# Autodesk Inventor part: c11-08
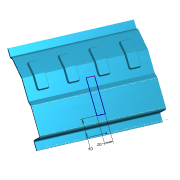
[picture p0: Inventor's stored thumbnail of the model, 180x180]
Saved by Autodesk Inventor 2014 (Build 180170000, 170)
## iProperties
Created: 2011-01
Part Number: c11-08
Material: Aluminum 6061
Document SubType Name: Sheet Metal
Designer: Thom Tremblay
Density: 2.71 g/cm^3
Sheet Metal Rule: Aluminum - 3.4mm
Appearance: Turquoise
Author: Thom Tremblay
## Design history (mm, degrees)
node "Contour Flange1"
  sketch "Sketch1"
    geometry: L1 (0, 0)-(20, 0); L2 (20, 0)-(20, 30); L3 (20, 30)-(90, 30); L4 (100.392, 24)-(150, 24); L5 (150, 24)-(200, 5.801); L6 (200, 5.801)-(200, 0); L7 (200, 0)-(220, 0); L8 (-200, 0)-(-200, 73.265); L9 (90, 30)-(100.392, 24); 1 further point
    constraints: 18 end point, 3 collinear, 3 parallel, 2 perpendicular, 1 coincident, 1 horizontal, 1 horizontal alignment
    dimensions: "d5" = 20 distance of L1.start L1.end; "d6" = 30 distance of L1.end L2.end; "d7" = 70 distance of L2.end L3.end; "d9" = 220 distance of L7.end point (0, 0); "d11" = 20 deg angle of L5 L4; "d12" = 200 distance from line of point (0, 0) L8; "d13" = 6 vertical distance of L3.end L4.start; "d14" = 130 distance from line of L4.end L2; "d15" = 30 deg angle of L9 L3
sketch "Sketch3" dims "d35" = 10
  geometry: L1 (-100.928, -300)-(-100.928, 0) reference; L2 (-100.928, 0)-(-82.928, 0) reference; 4 further points
  constraints: 1 vertical, 3 other
  dimensions: "d28" = 150 distance from line of point (49.072, -40) L1; "d29" = 40 distance from line of L2 point (49.072, -40); "d32" = 73 distance of point (49.072, -40) point (49.072, -113)
node "Unfold1"
feature "iFeature4:1"
node "Refold1"
sketch "Cut Sketch"
  geometry: L1 (63.153, 0)-(63.153, -300) reference; L2 (0, 0)-(63.153, 0) reference; L3 (0, 0)-(0, -300) reference; L4 (63.153, -300)-(0, -300) reference; L5 (14.6, -140)-(96.274, -140); L6 (96.274, -140)-(96.274, -160); L7 (96.274, -160)-(14.6, -160); L8 (14.6, -160)-(14.6, -140); L9 (-25.4, -300)-(-25.4, 0) reference; 2 further points
  constraints: 8 end point, 2 midpoint, 2 parallel, 1 horizontal, 1 horizontal alignment, 1 perpendicular
  dimensions: "d37" = 20 distance of L7.end L5.start; "d38" = 40 distance from line of point (-25.4, -150) L8
body "Solid2"
face "Plate2" dims "d16" = 3.4 (= BendReliefWidth), "d17" = 1.7 (= BendReliefDepth), "d18" = 6.8 (= MinimumRemnant), "d19" = 2 (= BendRadius), "d20" = 300, "d21" = 2 (= BendRadius), "d22" = 3.4, "d23" = 13.6 (= CornerReliefSize), "d24" = 3.4 (= GapSize), "d25" = 2 (= JacobiRadiusSize), "SeamGap" = 0.01, "Thickness" = 3.4 (derived)
bend "Bend1" dims "d16" = 3.4 (= BendReliefWidth), "d17" = 1.7 (= BendReliefDepth), "d18" = 6.8 (= MinimumRemnant), "d19" = 2 (= BendRadius), "d21" = 2 (= BendRadius), "d22" = 3.4, "SeamGap" = 0.01, "Thickness" = 3.4 (derived)
feature "Corner1" dims "d22" = 3.4, "d23" = 13.6 (= CornerReliefSize), "d24" = 3.4 (= GapSize), "d25" = 2 (= JacobiRadiusSize)
other parameters: "BendRadius" = 2 (derived), "BendReliefWidth" = 3.4 (= Thickness), "BendReliefDepth" = 1.7 (= 0.5 x Thickness), "CornerReliefSize" = 13.6 (= 4 x Thickness), "MinimumRemnant" = 6.8 (= 2 x Thickness), "TransitionRadius" = 2 (= BendRadius), "JacobiRadiusSize" = 2 (= BendRadius), "GapSize" = 3.4 (= Thickness), "d4" = 2 (= BendRadius), "d42" = 0
